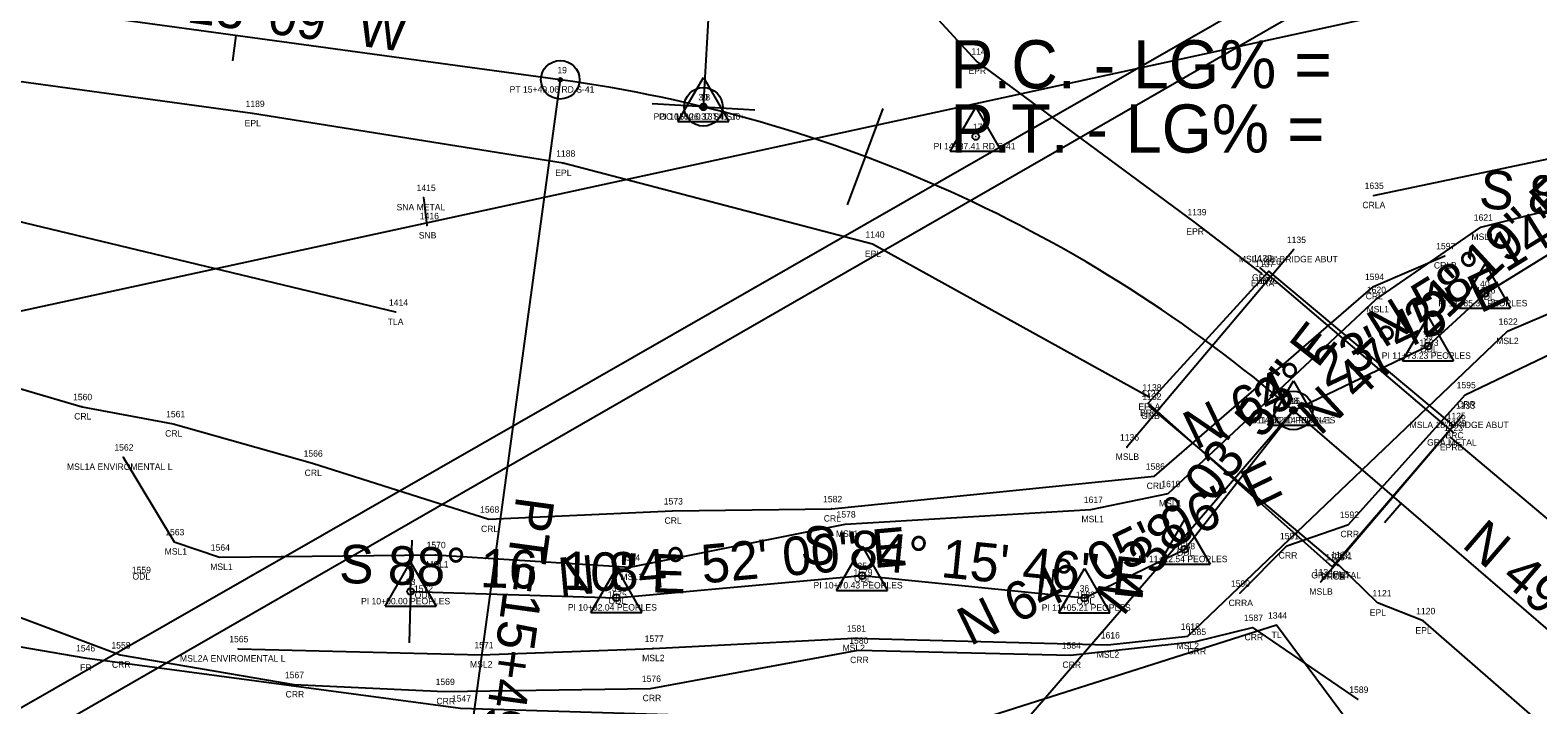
# Model space of a CAD drawing. Extents: x 1812340 to 1815011, y 1177659 to 1180159.
# Drawn here: x 1813558.8 to 1813793.4, y 1178660 to 1178765.1 of the extents above; entities that cross this region are included whole.
import ezdxf

# ---------------------------------------------------------------- set-up
doc = ezdxf.new("R2010")
doc.units = 0
for name, color, linetype in [('RD_EX_BldgApp', 7, 'Continuous'), ('RD_EX_BldgApp_txCode', 7, 'Continuous'), ('RD_EX_Bridge', 7, 'Continuous'), ('RD_EX_Bridge_txCode', 7, 'Continuous'), ('RD_EX_Fence_Other', 7, 'Continuous'), ('RD_EX_Fence_Other_txCode', 7, 'Continuous'), ('RD_EX_GuardRail', 7, 'Continuous'), ('RD_EX_GuardRail_txCode', 7, 'Continuous'), ('RD_EX_H2O', 7, 'Continuous'), ('RD_EX_H2O_txCode', 7, 'Continuous'), ('RD_EX_Misc', 7, 'Continuous'), ('RD_EX_Misc_txCode', 7, 'Continuous'), ('RD_EX_Road', 7, 'Continuous'), ('RD_EX_Road_txCode', 7, 'Continuous'), ('RD_EX_UT', 7, 'Continuous'), ('RD_EX_VEG', 7, 'Continuous'), ('RD_EX_VEG_txCode', 7, 'Continuous'), ('RD_HC_CL', 7, 'Continuous'), ('RD_HC_Data', 7, 'Continuous'), ('RD_HC_Data_Tic', 7, 'Continuous'), ('RD_HC_txCode', 7, 'Continuous'), ('RD_SMD_Locator', 7, 'Continuous')]:
    doc.layers.add(name, color=color, linetype=linetype)

msp = doc.modelspace()

# ---------------------------------------------------------------- linework, layer by layer
at = {"layer": 'RD_EX_BldgApp'}
msp.add_line((1813619.98, 1178739.01), (1813620.52, 1178734.63), dxfattribs=at)
at = {"layer": 'RD_EX_Bridge'}
msp.add_lwpolyline([(1813761.42, 1178681.53), (1813780.29, 1178703.5), (1813751.53, 1178727.56), (1813732.76, 1178707), (1813761.42, 1178681.53)], dxfattribs=at)
at = {"layer": 'RD_EX_Fence_Other'}
msp.add_lwpolyline([(1813495.44, 1178671.73), (1813524.97, 1178674.61), (1813567.3, 1178667.34), (1813625.77, 1178659.53), (1813676.75, 1178657.94), (1813689.16, 1178653.47)], dxfattribs=at)
at = {"layer": 'RD_EX_GuardRail'}
for p, q in [((1813780.35, 1178702.39), (1813750.18, 1178728.06)), ((1813762.33, 1178681.71), (1813732.93, 1178706.52))]:
    msp.add_line(p, q, dxfattribs=at)
at = {"layer": 'RD_EX_H2O'}
for points in [[(1813767.83, 1178739.34), (1813802.7, 1178746.65), (1813832.24, 1178749.11), (1813880.12, 1178745.59), (1813913.04, 1178737.89)], [(1813499.62, 1178706.37), (1813533.11, 1178716.31), (1813566.87, 1178706.45), (1813581.02, 1178703.79), (1813602.73, 1178697.66), (1813630.18, 1178688.94), (1813658.74, 1178690.22), (1813683.52, 1178690.56), (1813733.77, 1178695.63), (1813767.86, 1178725.16), (1813778.94, 1178729.95)], [(1813747.03, 1178677.41), (1813754.34, 1178684.8), (1813763.95, 1178688.13), (1813782.12, 1178708.31), (1813807.89, 1178720.63), (1813829.02, 1178714.89), (1813841.06, 1178713.13), (1813882.92, 1178708.73), (1813906.37, 1178716.29)], [(1813494.93, 1178677.14), (1813538.08, 1178685.02), (1813548.67, 1178684.4), (1813554.06, 1178674.83), (1813572.78, 1178667.8), (1813599.8, 1178663.18), (1813623.26, 1178662.12), (1813655.35, 1178662.6), (1813687.65, 1178668.53), (1813720.68, 1178667.78), (1813740.16, 1178669.89), (1813749.02, 1178672.08), (1813765.42, 1178660.89)]]:
    msp.add_lwpolyline(points, dxfattribs=at)
at = {"layer": 'RD_EX_Misc'}
for p, q in [((1813755.42, 1178730.93), (1813729.48, 1178700.17)), ((1813781.72, 1178705.12), (1813759.62, 1178679.18))]:
    msp.add_line(p, q, dxfattribs=at)
for points in [[(1813405.71, 1178572.74), (1813779.17, 1178786.7), (1813799.35, 1179222.21)], [(1813408.47, 1178567.92), (1813786.33, 1178785.29), (1813804.76, 1179221.83)], [(1813573.26, 1178698.61), (1813581.18, 1178685.42), (1813588.27, 1178683.03), (1813621.87, 1178683.41), (1813652.09, 1178681.47), (1813685.62, 1178688.18), (1813723.85, 1178690.46), (1813735.91, 1178692.91), (1813768.22, 1178723.13), (1813784.54, 1178734.4), (1813800.79, 1178738.46), (1813839.24, 1178736.87), (1813863.9, 1178734.39), (1813884.49, 1178732.56), (1813903.28, 1178733.23)], [(1813591.15, 1178668.77), (1813628.98, 1178667.84), (1813655.76, 1178668.83), (1813686.95, 1178670.41), (1813726.51, 1178669.36), (1813738.94, 1178670.71), (1813788.68, 1178718.19), (1813806.25, 1178725.66), (1813819.18, 1178726.19), (1813847.08, 1178721.31), (1813860.38, 1178717.65), (1813871.97, 1178724.25), (1813883.92, 1178723.48), (1813902.67, 1178722.42)]]:
    msp.add_lwpolyline(points, dxfattribs=at)
at = {"layer": 'RD_EX_Road'}
for points in [[(1813750.48, 1178727.17), (1813739.94, 1178735.23), (1813706.04, 1178760.25), (1813693.68, 1178773.78), (1813687.15, 1178785.68), (1813683.91, 1178796.53), (1813681.81, 1178824.01), (1813682.76, 1178849.48), (1813684.82, 1178900.28), (1813687.23, 1178946.66), (1813689.58, 1178995.92), (1813691.79, 1179045.45)], [(1813732.94, 1178707.95), (1813689.88, 1178731.75), (1813641.71, 1178744.36), (1813593.37, 1178752.09), (1813544.49, 1178758.77), (1813495.45, 1178766.29), (1813446.8, 1178774.66), (1813426.54, 1178777.95), (1813403.21, 1178782.55), (1813398.65, 1178783.84), (1813350.68, 1178796.09), (1813343.23, 1178797.92), (1813318.7, 1178804.23), (1813303.26, 1178808.85), (1813256.8, 1178823.17), (1813209.81, 1178838.91), (1813163.27, 1178855.57)], [(1814076.45, 1178427.4), (1814038.86, 1178461.87), (1814001.83, 1178496.62), (1813965.15, 1178531.54), (1813928.08, 1178567.1), (1813892.01, 1178601.23), (1813854.54, 1178636.51), (1813817.44, 1178670.03), (1813779.87, 1178701.64)], [(1813577.25, 1178474.27), (1813618.17, 1178504.26), (1813659.38, 1178535.26), (1813701.1, 1178565.69), (1813742.11, 1178594.54), (1813782.72, 1178623.8), (1813791.22, 1178630.12), (1813798.98, 1178638.62), (1813801.09, 1178645.46), (1813800.26, 1178651.57), (1813775.58, 1178673.13), (1813768.46, 1178675.91), (1813762.33, 1178681.89)]]:
    msp.add_lwpolyline(points, dxfattribs=at)
at = {"layer": 'RD_EX_UT'}
msp.add_lwpolyline([(1813817.45, 1178777.9), (1813490.2, 1178706.76), (1813294.33, 1178669.42)], dxfattribs=at)
at = {"layer": 'RD_EX_VEG'}
for points in [[(1813615.69, 1178721.17), (1813497.56, 1178749.53), (1813481.72, 1178712.39)], [(1813569.58, 1178500.76), (1813635.35, 1178535.15), (1813737.8, 1178606.06), (1813775.9, 1178641.25), (1813752.75, 1178672.45), (1813690.46, 1178652.62), (1813708.11, 1178634.09), (1813540.71, 1178531.72)]]:
    msp.add_lwpolyline(points, dxfattribs=at)
at = {"layer": 'RD_HC_CL'}
for p, q in [((1813663.56, 1178753.12), (1813680.53, 1179052.64)), ((1813641.28, 1178757.34), (1813538.22, 1178771.42)), ((1813785.2, 1178724.07), (1813802.21, 1178734.6)), ((1813776.33, 1178715.9), (1813785.2, 1178724.07)), ((1813755.38, 1178705.86), (1813776.33, 1178715.9)), ((1813738.45, 1178684.24), (1813755.38, 1178705.86)), ((1813850.52, 1178623.8), (1813755.38, 1178705.86)), ((1813722.87, 1178676.67), (1813738.45, 1178684.24)), ((1813650.02, 1178676.71), (1813688.26, 1178680.15)), ((1813688.26, 1178680.15), (1813722.87, 1178676.67)), ((1813618, 1178677.68), (1813650.02, 1178676.71))]:
    msp.add_line(p, q, dxfattribs=at)
msp.add_arc((1813611.44, 1178539), 220.37, 49.2184, 82.2191, dxfattribs=at)
at = {"layer": 'RD_HC_Data'}
for p, q in [((1813641.28, 1178757.34), (1813625.58, 1178642.45)), ((1813659.59, 1178750.82), (1813663.56, 1178757.7)), ((1813663.56, 1178757.7), (1813667.53, 1178750.82)), ((1813701.98, 1178746.21), (1813705.95, 1178753.09)), ((1813705.95, 1178753.09), (1813709.92, 1178746.21)), ((1813659.59, 1178750.82), (1813667.53, 1178750.82)), ((1813701.98, 1178746.21), (1813709.92, 1178746.21)), ((1813781.23, 1178721.78), (1813785.2, 1178728.66)), ((1813785.2, 1178728.66), (1813789.17, 1178721.78)), ((1813781.23, 1178721.78), (1813789.17, 1178721.78)), ((1813772.35, 1178713.61), (1813776.33, 1178720.49)), ((1813776.33, 1178720.49), (1813780.3, 1178713.61)), ((1813772.35, 1178713.61), (1813780.3, 1178713.61)), ((1813751.41, 1178703.57), (1813755.38, 1178710.45)), ((1813755.38, 1178710.45), (1813759.35, 1178703.57)), ((1813755.38, 1178705.86), (1813679.19, 1178617.54)), ((1813751.41, 1178703.57), (1813759.35, 1178703.57)), ((1813734.48, 1178681.95), (1813738.45, 1178688.83)), ((1813738.45, 1178688.83), (1813742.42, 1178681.95)), ((1813684.29, 1178677.85), (1813688.26, 1178684.73)), ((1813688.26, 1178684.73), (1813692.23, 1178677.85)), ((1813614.03, 1178675.39), (1813618, 1178682.27)), ((1813618, 1178682.27), (1813621.97, 1178675.39)), ((1813646.05, 1178674.42), (1813650.02, 1178681.3)), ((1813650.02, 1178681.3), (1813653.99, 1178674.42)), ((1813718.89, 1178674.38), (1813722.87, 1178681.26)), ((1813722.87, 1178681.26), (1813726.83, 1178674.38)), ((1813734.48, 1178681.95), (1813742.42, 1178681.95)), ((1813684.29, 1178677.85), (1813692.23, 1178677.85)), ((1813614.03, 1178675.39), (1813621.97, 1178675.39)), ((1813646.05, 1178674.42), (1813653.99, 1178674.42)), ((1813718.89, 1178674.38), (1813726.83, 1178674.38))]:
    msp.add_line(p, q, dxfattribs=at)
for centre, radius in [((1813641.28, 1178757.34), 3), ((1813641.28, 1178757.34), 0.282), ((1813663.56, 1178753.12), 3), ((1813663.56, 1178753.12), 0.529), ((1813663.56, 1178753.12), 0.282), ((1813705.95, 1178748.5), 0.529), ((1813785.2, 1178724.07), 0.529), ((1813776.33, 1178715.9), 0.529), ((1813755.38, 1178705.86), 3), ((1813755.38, 1178705.86), 0.529), ((1813755.38, 1178705.86), 0.282), ((1813738.45, 1178684.24), 0.529), ((1813688.26, 1178680.15), 0.529), ((1813618, 1178677.68), 0.529), ((1813650.02, 1178676.71), 0.529), ((1813722.87, 1178676.67), 0.529)]:
    msp.add_circle(centre, radius, dxfattribs=at)
at = {"layer": 'RD_HC_Data_Tic'}
for p, q in [((1813590.81, 1178764.23), (1813590.26, 1178760.27)), ((1813663.56, 1178753.12), (1813655.57, 1178753.57)), ((1813663.56, 1178753.12), (1813671.54, 1178752.66)), ((1813688.75, 1178745.36), (1813691.55, 1178752.85)), ((1813688.75, 1178745.36), (1813685.94, 1178737.87)), ((1813772.14, 1178691.4), (1813769.53, 1178688.37)), ((1813618, 1178677.68), (1813618.24, 1178685.67)), ((1813717.68, 1178677.19), (1813718.08, 1178681.17)), ((1813618, 1178677.68), (1813617.75, 1178669.68))]:
    msp.add_line(p, q, dxfattribs=at)
at = {"layer": 'RD_SMD_Locator'}
for centre in [(1813706.04, 1178760.25), (1813641.28, 1178757.34), (1813593.37, 1178752.09), (1813663.56, 1178753.12), (1813663.56, 1178753.12), (1813705.95, 1178748.5), (1813641.71, 1178744.36), (1813619.98, 1178739.01), (1813767.83, 1178739.34), (1813739.94, 1178735.23), (1813620.52, 1178734.63), (1813784.54, 1178734.4), (1813689.88, 1178731.75), (1813755.42, 1178730.93), (1813750.18, 1178728.06), (1813778.94, 1178729.95), (1813750.48, 1178727.17), (1813751.53, 1178727.56), (1813767.86, 1178725.16), (1813785.2, 1178724.07), (1813785.2, 1178724.07), (1813615.69, 1178721.17), (1813768.22, 1178723.13), (1813788.68, 1178718.19), (1813776.33, 1178715.9), (1813776.33, 1178715.9), (1813732.76, 1178707), (1813732.94, 1178707.95), (1813782.12, 1178708.31), (1813566.87, 1178706.45), (1813732.93, 1178706.52), (1813755.38, 1178705.86), (1813755.38, 1178705.86), (1813781.72, 1178705.12), (1813581.02, 1178703.79), (1813780.29, 1178703.5), (1813780.35, 1178702.39), (1813729.48, 1178700.17), (1813779.87, 1178701.64), (1813573.26, 1178698.61), (1813602.73, 1178697.66), (1813733.77, 1178695.63), (1813735.91, 1178692.91), (1813683.52, 1178690.56), (1813630.18, 1178688.94), (1813658.74, 1178690.22), (1813685.62, 1178688.18), (1813723.85, 1178690.46), (1813763.95, 1178688.13), (1813581.18, 1178685.42), (1813738.45, 1178684.24), (1813738.45, 1178684.24), (1813754.34, 1178684.8), (1813588.27, 1178683.03), (1813621.87, 1178683.41), (1813652.09, 1178681.47), (1813761.42, 1178681.53), (1813761.42, 1178681.53), (1813762.33, 1178681.89), (1813762.33, 1178681.71), (1813575.96, 1178680.52), (1813688.26, 1178680.15), (1813688.26, 1178680.15), (1813759.62, 1178679.18), (1813618, 1178677.68), (1813619.86, 1178677.62), (1813650.02, 1178676.71), (1813650.02, 1178676.71), (1813722.87, 1178676.67), (1813722.87, 1178676.67), (1813747.03, 1178677.41), (1813768.46, 1178675.91), (1813749.02, 1178672.08), (1813752.75, 1178672.45), (1813775.58, 1178673.13), (1813686.95, 1178670.41), (1813726.51, 1178669.36), (1813738.94, 1178670.71), (1813740.16, 1178669.89), (1813567.3, 1178667.34), (1813572.78, 1178667.8), (1813591.15, 1178668.77), (1813628.98, 1178667.84), (1813655.76, 1178668.83), (1813687.65, 1178668.53), (1813720.68, 1178667.78), (1813599.8, 1178663.18), (1813655.35, 1178662.6), (1813623.26, 1178662.12), (1813765.42, 1178660.89)]:
    msp.add_circle(centre, 0.001, dxfattribs=at)

# ---------------------------------------------------------------- texts
at = {"layer": 'RD_EX_BldgApp_txCode'}
for s, p in [('1415', (1813618.92, 1178740.01)), ('SNA METAL', (1813615.81, 1178737.01)), ('1416', (1813619.43, 1178735.63)), ('SNB', (1813619.26, 1178732.63))]:
    msp.add_text(s, height=1, dxfattribs=at).set_placement(p)
at = {"layer": 'RD_EX_Bridge_txCode'}
for s, p in [('1126', (1813750.44, 1178728.56)), ('BRC', (1813750.27, 1178725.56)), ('1127', (1813731.7, 1178708)), ('BRC', (1813731.51, 1178705)), ('1125', (1813779.22, 1178704.5)), ('BRC', (1813779.04, 1178701.5)), ('1124', (1813760.36, 1178682.53)), ('1128', (1813760.36, 1178682.53)), ('BRCA', (1813759.68, 1178679.53)), ('BRCB', (1813759.7, 1178679.53))]:
    msp.add_text(s, height=1, dxfattribs=at).set_placement(p)
at = {"layer": 'RD_EX_Fence_Other_txCode'}
for s, p in [('1546', (1813565.93, 1178668.34)), ('FR', (1813566.55, 1178665.34)), ('1547', (1813624.42, 1178660.53))]:
    msp.add_text(s, height=1, dxfattribs=at).set_placement(p)
at = {"layer": 'RD_EX_GuardRail_txCode'}
for s, p in [('1130', (1813749.08, 1178729.06)), ('GRB', (1813748.93, 1178726.06)), ('1132', (1813731.87, 1178707.52)), ('GRB', (1813731.68, 1178704.52)), ('1129', (1813779.28, 1178703.39)), ('GRA METAL', (1813776.18, 1178700.39)), ('1131', (1813761.55, 1178682.71)), ('GRA METAL', (1813758.16, 1178679.71))]:
    msp.add_text(s, height=1, dxfattribs=at).set_placement(p)
at = {"layer": 'RD_EX_H2O_txCode'}
for s, p in [('1635', (1813766.46, 1178740.34)), ('CRLA', (1813766.11, 1178737.34)), ('1597', (1813777.59, 1178730.95)), ('CRLB', (1813777.24, 1178727.95)), ('1594', (1813766.51, 1178726.16)), ('CRL', (1813766.63, 1178723.16)), ('1596', (1813783.83, 1178724.07)), ('ODL', (1813783.96, 1178723.07)), ('1593', (1813774.98, 1178715.9)), ('ODL', (1813775.08, 1178714.9)), ('1595', (1813780.78, 1178709.31)), ('1560', (1813565.46, 1178707.45)), ('CRR', (1813780.87, 1178706.31)), ('CRL', (1813565.64, 1178704.45)), ('1561', (1813579.94, 1178704.79)), ('CRL', (1813579.79, 1178701.79)), ('1566', (1813601.34, 1178698.66)), ('1586', (1813732.4, 1178696.63)), ('CRL', (1813601.5, 1178695.66)), ('CRL', (1813732.54, 1178693.63)), ('1568', (1813628.81, 1178689.94)), ('1573', (1813657.39, 1178691.22)), ('1582', (1813682.18, 1178691.56)), ('CRL', (1813657.51, 1178688.22)), ('CRL', (1813682.29, 1178688.56)), ('1592', (1813762.61, 1178689.13)), ('CRL', (1813628.95, 1178686.94)), ('1591', (1813753.28, 1178685.8)), ('CRR', (1813762.7, 1178686.13)), ('1588', (1813737.1, 1178684.24)), ('ODL', (1813737.2, 1178683.24)), ('CRR', (1813753.09, 1178682.8)), ('1559', (1813574.61, 1178680.52)), ('1579', (1813686.91, 1178680.15)), ('ODL', (1813574.71, 1178679.52)), ('ODL', (1813687.01, 1178679.15)), ('1590', (1813745.65, 1178678.41)), ('1572', (1813618.51, 1178677.62)), ('ODL', (1813618.62, 1178676.62)), ('1575', (1813648.67, 1178676.71)), ('ODL', (1813648.78, 1178675.71)), ('1583', (1813721.52, 1178676.67)), ('ODL', (1813721.62, 1178675.67)), ('CRRA', (1813745.29, 1178675.41)), ('1587', (1813747.67, 1178673.08)), ('1585', (1813738.81, 1178670.89)), ('1558', (1813571.43, 1178668.8)), ('1580', (1813686.26, 1178669.53)), ('1584', (1813719.33, 1178668.78)), ('CRR', (1813747.77, 1178670.08)), ('CRR', (1813686.39, 1178666.53)), ('CRR', (1813738.9, 1178667.89)), ('CRR', (1813571.52, 1178665.8)), ('1567', (1813598.43, 1178664.18)), ('CRR', (1813719.43, 1178665.78)), ('1569', (1813621.89, 1178663.12)), ('1576', (1813653.98, 1178663.6)), ('1589', (1813764.07, 1178661.89)), ('CRR', (1813598.54, 1178661.18)), ('CRR', (1813622.01, 1178660.12)), ('CRR', (1813654.1, 1178660.6))]:
    msp.add_text(s, height=1, dxfattribs=at).set_placement(p)
at = {"layer": 'RD_EX_Misc_txCode'}
for s, p in [('1621', (1813783.45, 1178735.4)), ('1135', (1813754.36, 1178731.93)), ('MSL1', (1813783.08, 1178732.4)), ('MSLA 28" BRIDGE ABUT', (1813746.88, 1178728.93)), ('1620', (1813766.81, 1178724.13)), ('MSL1', (1813766.76, 1178721.13)), ('1622', (1813787.31, 1178719.19)), ('MSL2', (1813786.94, 1178716.19)), ('1133', (1813780.66, 1178706.12)), ('MSLA 18" BRIDGE ABUT', (1813773.47, 1178703.12)), ('1562', (1813571.89, 1178699.61)), ('1136', (1813728.39, 1178701.17)), ('MSL1A ENVIROMENTAL L', (1813564.51, 1178696.61)), ('MSLB', (1813727.72, 1178698.17)), ('1619', (1813734.82, 1178693.91)), ('1617', (1813722.76, 1178691.46)), ('MSL1', (1813734.45, 1178690.91)), ('1578', (1813684.28, 1178689.18)), ('MSL1', (1813722.39, 1178688.46)), ('1563', (1813579.81, 1178686.42)), ('MSL1', (1813684.17, 1178686.18)), ('MSL1', (1813579.72, 1178683.42)), ('1564', (1813586.9, 1178684.03)), ('1570', (1813620.48, 1178684.41)), ('1574', (1813650.75, 1178682.47)), ('MSL1', (1813586.81, 1178681.03)), ('MSL1', (1813620.41, 1178681.41)), ('1134', (1813758.56, 1178680.18)), ('MSL1', (1813650.64, 1178679.47)), ('MSLB', (1813757.86, 1178677.18)), ('1581', (1813685.89, 1178671.41)), ('1618', (1813737.85, 1178671.71)), ('1565', (1813589.77, 1178669.77)), ('1571', (1813627.92, 1178668.84)), ('1577', (1813654.41, 1178669.83)), ('MSL2', (1813685.21, 1178668.41)), ('1616', (1813725.4, 1178670.36)), ('MSL2', (1813737.2, 1178668.71)), ('MSL2A ENVIROMENTAL L', (1813582.11, 1178666.77)), ('MSL2', (1813654.02, 1178666.83)), ('MSL2', (1813724.77, 1178667.36)), ('MSL2', (1813627.24, 1178665.84))]:
    msp.add_text(s, height=1, dxfattribs=at).set_placement(p)
at = {"layer": 'RD_EX_Road_txCode'}
for s, p in [('1141', (1813705.26, 1178761.25)), ('EPR', (1813704.81, 1178758.25)), ('1189', (1813592.31, 1178753.09)), ('EPL', (1813592.16, 1178750.09)), ('1188', (1813640.65, 1178745.36)), ('EPL', (1813640.5, 1178742.36)), ('1139', (1813738.88, 1178736.23)), ('1140', (1813688.78, 1178732.75)), ('EPR', (1813738.71, 1178733.23)), ('EPL', (1813688.68, 1178729.75)), ('1137', (1813749.42, 1178728.17)), ('EPRA', (1813748.76, 1178725.17)), ('1138', (1813731.88, 1178708.95)), ('EPLA', (1813731.25, 1178705.95)), ('1123', (1813778.8, 1178702.64)), ('EPRB', (1813778.17, 1178699.64)), ('1122', (1813761.26, 1178682.89)), ('EPLB', (1813760.65, 1178679.89)), ('1121', (1813767.68, 1178676.91)), ('EPL', (1813767.26, 1178673.91)), ('1120', (1813774.48, 1178674.13)), ('EPL', (1813774.37, 1178671.13))]:
    msp.add_text(s, height=1, dxfattribs=at).set_placement(p)
at = {"layer": 'RD_EX_VEG_txCode'}
for s, p in [('1414', (1813614.63, 1178722.17)), ('TLA', (1813614.43, 1178719.17)), ('1344', (1813751.41, 1178673.45)), ('TL', (1813751.98, 1178670.45))]:
    msp.add_text(s, height=1, dxfattribs=at).set_placement(p)
at = {"layer": 'RD_HC_Data'}
for s, rotation, p in [('N 82%%d 13\' 09" W', 352.2191, (1813560.83, 1178769.34)), ('N 58%%d 14\' 53" E', 31.752, (1813769.39, 1178715.47)), ('N 47%%d 21\' 19" E', 42.6448, (1813759.51, 1178701.77)), ('S 84%%d 09\' 51" E', 354.1642, (1813784.12, 1178737.46)), ('N 64%%d 23\' 45" E', 25.6042, (1813740.19, 1178699.69)), ('N 38%%d 03\' 53" E', 51.9353, (1813728.88, 1178673.64)), ('N 64%%d 05\' 06" E', 25.9149, (1813705.05, 1178669.13)), ('PT=15+49.06', 262.2191, (1813634.46, 1178692.67)), ('N 49%%d 13\' 06" W', 319.2184, (1813781.4, 1178684.74)), ('N 84%%d 52\' 00" E', 5.1334, (1813641.18, 1178676.92)), ('S 84%%d 15\' 46" E', 354.2627, (1813678.55, 1178682.13)), ('S 88%%d 16\' 10" E', 358.2694, (1813606.81, 1178679.02))]:
    msp.add_text(s, height=6, rotation=rotation, dxfattribs=at).set_placement(p)
for s, p in [('P.C. - LG% = ', (1813702, 1178756)), ('P.T. - LG% = ', (1813702, 1178746))]:
    msp.add_text(s, height=7.5, dxfattribs=at).set_placement(p)
at = {"layer": 'RD_HC_txCode'}
for s, p in [('19', (1813640.83, 1178758.34)), ('PT 15+49.06 RD S-41', (1813633.4, 1178755.34)), ('30', (1813662.78, 1178754.12)), ('18', (1813663.11, 1178754.12)), ('POC 15+26.37 S41 10+', (1813655.81, 1178751.12)), ('PI 10+00.0 13TH ST', (1813656.62, 1178751.12)), ('17', (1813705.5, 1178749.5)), ('PI 14+87.41 RD S-41', (1813699.38, 1178746.5)), ('40', (1813784.43, 1178725.07)), ('PI 11+85.30 PEOPLES', (1813777.93, 1178722.07)), ('39', (1813775.59, 1178716.9)), ('PI 11+73.23 PEOPLES', (1813769.13, 1178713.9)), ('38', (1813754.65, 1178706.86)), ('16', (1813754.91, 1178706.86)), ('PC 14+22.14 RD S-41', (1813747.91, 1178703.86)), ('PI 11+50.00 PEOPLES', (1813748.03, 1178703.86)), ('37', (1813737.72, 1178685.24)), ('35', (1813687.53, 1178681.15)), ('PI 11+22.54 PEOPLES', (1813731.25, 1178682.24)), ('33', (1813617.26, 1178678.68)), ('PI 10+70.43 PEOPLES', (1813680.7, 1178678.15)), ('PI 10+00.00 PEOPLES', (1813610.28, 1178675.68)), ('34', (1813649.29, 1178677.71)), ('36', (1813722.11, 1178677.67)), ('PI 10+32.04 PEOPLES', (1813642.46, 1178674.71)), ('PI 11+05.21 PEOPLES', (1813716.2, 1178674.67))]:
    msp.add_text(s, height=1, dxfattribs=at).set_placement(p)

doc.saveas('drawing.dxf')
